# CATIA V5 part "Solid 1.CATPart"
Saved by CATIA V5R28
Part number: Part6
Bounding box of the stored display mesh (mm): x -75 to 75.038, y 0 to 600, z -20 to 20
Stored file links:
  H:\Maskiningenjör\Examensarbete\Klart\Klart & Skickas\Solid 1.CATPart
  H:\Examensarbete\Catia filer\Klar assembly\Klara blad av SOLID med hal\BladDesign.CATPart
  H:\Examensarbete\FullAssembly_KlartMedStativ\Assembly_Fullt+Stativ.CATProduct
  H:\Maskiningenjör\Examensarbete\Klart\Klart & Skickas\HJALPMEDEL.CATPart
  H:\Maskiningenjör\Examensarbete\Klart\Stativ o allt\AssemblyBlad_OriginalDesign.CATProduct
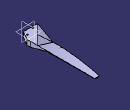
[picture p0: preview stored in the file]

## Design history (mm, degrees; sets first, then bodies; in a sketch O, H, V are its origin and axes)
Set1
  DatumPoint1 to DatumPoint3: linked copy from another document
Body1 (main body)
Body2 "Solid Blad"
  Solid1: solid without history
  Sketch1, origin (42.0318, 34.9839, 20), H (1, 0, 0), V (0, 1, 0), geometry linked from another document
  Hole1: placed by Sketch1, at (42.3349, 35.5089, 20) direction (0, 0, -1), diameter 12, through (limit type 3)
  Sketch2, origin (-26.4443, 12.7347, 20), H (1, 0, 0), V (0, 1, 0), geometry linked from another document
  Hole2: placed by Sketch2, at (-26.1412, 13.2597, 20) direction (0, 0, -1), diameter 12, through (limit type 3)
  Sketch3 "Positioning sketch - Assembly Hole.1" on face of Solid1, origin (42.0318, 34.9839, 20), H (1, 0, 0), V (0, 1, 0)
    point P1 (0.3031, 0.525)
    reference projected point E1 (0.3031, 0.525) from vertex of DatumPoint2
    coincidence: E1 P1
  Sketch4 "Positioning sketch - Assembly Hole.2" on face of Solid1, origin (-26.4443, 12.7347, 20), H (1, 0, 0), V (0, 1, 0)
    point P1 (0.3031, 0.525)
    reference projected point E1 (0.3031, 0.525) from vertex of DatumPoint3
    coincidence: E1 P1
